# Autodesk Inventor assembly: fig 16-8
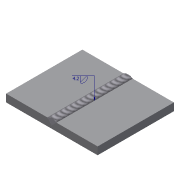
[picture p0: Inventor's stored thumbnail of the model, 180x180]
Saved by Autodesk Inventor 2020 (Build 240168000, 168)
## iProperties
Created: 2004-07
Part Number: fig 16-8
Document SubType Name: Weldment
Designer: CADCIM Technologies
Manufacturer: Standard
Standards Organization: Custom
Author: CADCIM Technologies
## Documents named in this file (2)
- D:\Autodesk Inventor_2020\Resources\Resources\Inventor_2020_Part\Inventor_2020_Part\c16_Inv_2020_prt\fig 16-8\fig 16-8.iam
- D:\Autodesk Inventor_2020\Resources\Resources\Inventor_2020_Part\Inventor_2020_Part\c16_Inv_2020_prt\fig 16-8\Plate.ipt
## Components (2 placed, 1 different names)
1. Plate:1 — Mate:1, Flush:1, Flush:2
2. Plate:2 — Mate:1, Flush:1, Flush:2
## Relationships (3: Flush 2, Mate 1)
- Mate:1: Plate:1 ↔ Plate:2
- Flush:1: Plate:1 ↔ Plate:2
- Flush:2: Plate:1 ↔ Plate:2
